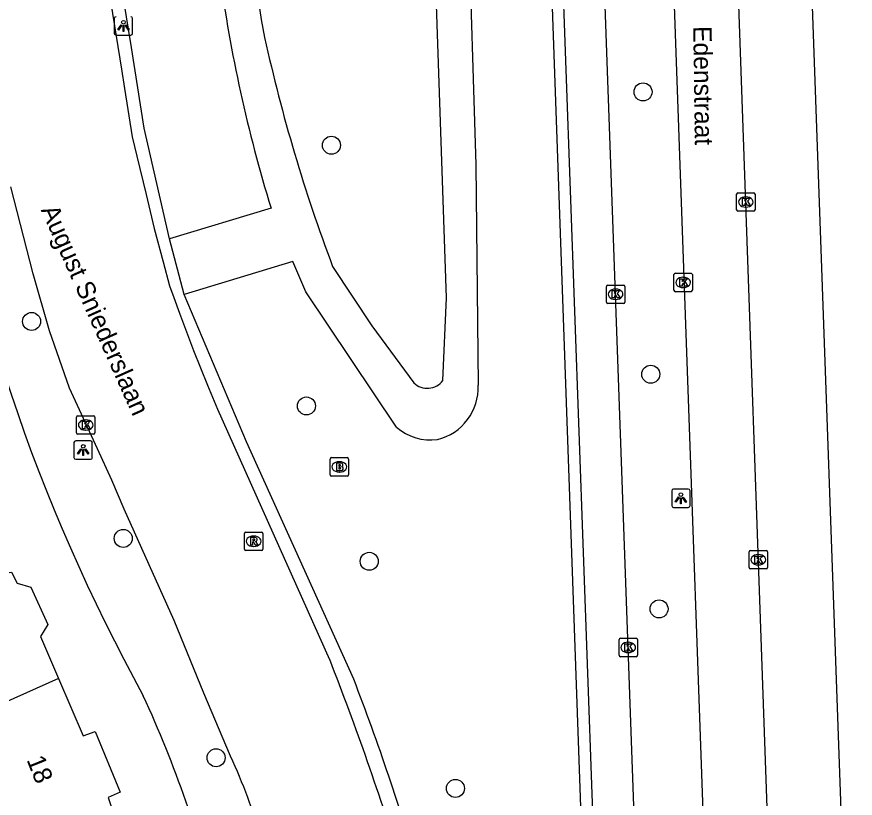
# Model space of a CAD drawing. Extents: x 160356 to 161355, y 381727 to 382845.
# Drawn here: x 161287.38 to 161332.94, y 382329.85 to 382372.29 of the extents above; entities that cross this region are included whole.
import ezdxf

# ---------------------------------------------------------------- set-up
doc = ezdxf.new("R2010")
doc.units = 0
for name, color, linetype in [('IMGEO_Boom', 7, 'Continuous'), ('IMGEO_Brandkraan', 7, 'Continuous'), ('IMGEO_Fietspad_gesloten', 7, 'Continuous'), ('IMGEO_Kolk', 7, 'Continuous'), ('IMGEO_Lichtpunt', 7, 'Continuous'), ('IMGEO_Openbare_ruimte_label', 7, 'Continuous'), ('IMGEO_Pand', 7, 'Continuous'), ('IMGEO_Pand_nummerreeks', 7, 'Continuous'), ('IMGEO_Rijbaan_lokaal_gesloten', 7, 'Continuous'), ('IMGEO_Rijbaan_lokaal_open', 7, 'Continuous'), ('IMGEO_Rioolput', 7, 'Continuous'), ('IMGEO_Voetpad_open', 7, 'Continuous')]:
    doc.layers.add(name, color=color, linetype=linetype)

msp = doc.modelspace()

# ---------------------------------------------------------------- linework, layer by layer
at = {"layer": 'IMGEO_Boom'}
for centre in [(161321.409, 382368.212), (161304.473, 382365.313), (161288.179, 382355.742), (161321.828, 382352.876), (161303.117, 382351.152), (161293.163, 382343.955), (161306.528, 382342.714), (161322.279, 382340.129), (161298.208, 382332.042), (161311.215, 382330.379)]:
    msp.add_circle(centre, 0.489, dxfattribs=at)
at = {"layer": 'IMGEO_Brandkraan'}
for p, q in [((161304.477, 382348.344), (161305.329, 382348.344)), ((161304.402, 382347.418), (161304.402, 382348.27)), ((161304.89, 382348.124), (161304.915, 382348.124)), ((161305.403, 382348.27), (161305.403, 382347.418)), ((161304.913, 382347.564), (161304.888, 382347.564)), ((161305.329, 382347.344), (161304.477, 382347.344))]:
    msp.add_line(p, q, dxfattribs=at)
for points in [[(161304.477, 382348.344), (161305.329, 382348.344)], [(161304.402, 382347.418), (161304.402, 382348.27)], [(161304.75, 382348.044), (161304.75, 382347.644), (161304.963, 382347.644)], [(161304.981, 382348.044), (161304.75, 382348.044)], [(161304.929, 382347.963), (161304.875, 382347.963), (161304.875, 382347.887)], [(161304.875, 382347.887), (161304.928, 382347.887)], [(161305.403, 382348.27), (161305.403, 382347.418)], [(161304.937, 382347.811), (161304.875, 382347.811), (161304.875, 382347.73)], [(161304.875, 382347.73), (161304.937, 382347.73)], [(161305.329, 382347.344), (161304.477, 382347.344)]]:
    msp.add_lwpolyline(points, dxfattribs=at)
for centre, radius, start, end in [((161304.479, 382348.268), 0.0765, 91.552, 178.448), ((161304.479, 382348.268), 0.0765, 91.552, 178.448), ((161305.327, 382348.268), 0.0765, 1.552, 88.448), ((161305.327, 382348.268), 0.0765, 1.552, 88.448), ((161304.93, 382347.925), 0.0379, 267.8285, 90.9355), ((161304.985, 382347.899), 0.145, 59.4692, 91.5367), ((161305.01, 382347.946), 0.0922, 285.5137, 58.1501), ((161305.015, 382347.754), 0.105, 301.3115, 78.989), ((161304.479, 382347.42), 0.0765, 181.552, 268.448), ((161304.479, 382347.42), 0.0765, 181.552, 268.448), ((161304.938, 382347.77), 0.0404, 269.8759, 90.5077), ((161304.969, 382347.895), 0.251, 268.6676, 293.5347), ((161305.327, 382347.42), 0.0765, 271.552, 358.448), ((161305.327, 382347.42), 0.0765, 271.552, 358.448)]:
    msp.add_arc(centre, radius, start, end, dxfattribs=at)
for centre, major_axis, ratio, start_param, end_param in [((161304.889, 382347.844), (-0.387, 0.002), 0.722429, 4.712389, 7.853982), ((161304.914, 382347.844), (-0.39, 0.002), 0.717154, 1.570796, 4.712389)]:
    msp.add_ellipse(centre, major_axis=major_axis, ratio=ratio, start_param=start_param, end_param=end_param, dxfattribs=at)
at = {"layer": 'IMGEO_Fietspad_gesloten'}
for points in [[(161321.926, 382301.113), (161318.45, 382398.178)], [(161322.18, 382266.442), (161320.188, 382290.699), (161319.95, 382294.602), (161319.771, 382298.34), (161319.579, 382303.861), (161316.294, 382395.637)]]:
    msp.add_lwpolyline(points, dxfattribs=at)
at = {"layer": 'IMGEO_Kolk'}
for p, q in [((161326.494, 382361.806), (161326.494, 382362.658)), ((161326.569, 382362.732), (161327.421, 382362.732)), ((161326.982, 382362.512), (161327.007, 382362.512)), ((161327.495, 382362.658), (161327.495, 382361.806)), ((161327.005, 382361.952), (161326.98, 382361.952)), ((161327.421, 382361.732), (161326.569, 382361.732)), ((161323.166, 382358.36), (161324.018, 382358.36)), ((161323.091, 382357.434), (161323.091, 382358.286)), ((161323.579, 382358.14), (161323.604, 382358.14)), ((161324.092, 382358.286), (161324.092, 382357.434)), ((161319.417, 382356.792), (161319.417, 382357.644)), ((161319.492, 382357.718), (161320.344, 382357.718)), ((161319.905, 382357.498), (161319.93, 382357.498)), ((161320.418, 382357.644), (161320.418, 382356.792)), ((161323.602, 382357.58), (161323.577, 382357.58)), ((161319.928, 382356.938), (161319.903, 382356.938)), ((161324.018, 382357.36), (161323.166, 382357.36)), ((161320.344, 382356.718), (161319.492, 382356.718)), ((161290.7, 382350.619), (161291.552, 382350.619)), ((161290.625, 382349.693), (161290.625, 382350.545)), ((161291.113, 382350.399), (161291.138, 382350.399)), ((161291.626, 382350.545), (161291.626, 382349.693)), ((161291.136, 382349.839), (161291.111, 382349.839)), ((161291.552, 382349.619), (161290.7, 382349.619)), ((161327.248, 382343.301), (161328.1, 382343.301)), ((161327.173, 382342.375), (161327.173, 382343.227)), ((161327.661, 382343.081), (161327.686, 382343.081)), ((161328.174, 382343.227), (161328.174, 382342.375)), ((161327.684, 382342.521), (161327.659, 382342.521)), ((161328.1, 382342.301), (161327.248, 382342.301)), ((161320.104, 382337.608), (161320.104, 382338.46)), ((161320.179, 382338.534), (161321.031, 382338.534)), ((161320.592, 382338.314), (161320.617, 382338.314)), ((161321.105, 382338.46), (161321.105, 382337.608)), ((161321.031, 382337.534), (161320.179, 382337.534)), ((161320.615, 382337.754), (161320.59, 382337.754))]:
    msp.add_line(p, q, dxfattribs=at)
for points in [[(161326.494, 382361.806), (161326.494, 382362.658)], [(161326.569, 382362.732), (161327.421, 382362.732)], [(161326.815, 382362.432), (161326.938, 382362.432), (161326.938, 382362.281), (161327.068, 382362.432), (161327.232, 382362.432), (161327.086, 382362.281), (161327.239, 382362.032), (161327.087, 382362.032), (161327.002, 382362.196), (161326.938, 382362.129), (161326.938, 382362.032), (161326.815, 382362.032), (161326.815, 382362.432)], [(161327.495, 382362.658), (161327.495, 382361.806)], [(161327.421, 382361.732), (161326.569, 382361.732)], [(161323.166, 382358.36), (161324.018, 382358.36)], [(161323.091, 382357.434), (161323.091, 382358.286)], [(161323.412, 382358.06), (161323.535, 382358.06), (161323.535, 382357.909), (161323.665, 382358.06), (161323.829, 382358.06), (161323.683, 382357.909), (161323.836, 382357.66), (161323.684, 382357.66), (161323.599, 382357.824), (161323.535, 382357.757), (161323.535, 382357.66), (161323.412, 382357.66), (161323.412, 382358.06)], [(161324.092, 382358.286), (161324.092, 382357.434)], [(161319.417, 382356.792), (161319.417, 382357.644)], [(161319.492, 382357.718), (161320.344, 382357.718)], [(161319.738, 382357.418), (161319.861, 382357.418), (161319.861, 382357.267), (161319.991, 382357.418), (161320.155, 382357.418), (161320.009, 382357.267), (161320.162, 382357.018), (161320.01, 382357.018), (161319.925, 382357.182), (161319.861, 382357.115), (161319.861, 382357.018), (161319.738, 382357.018), (161319.738, 382357.418)], [(161320.418, 382357.644), (161320.418, 382356.792)], [(161324.018, 382357.36), (161323.166, 382357.36)], [(161320.344, 382356.718), (161319.492, 382356.718)], [(161290.7, 382350.619), (161291.552, 382350.619)], [(161290.625, 382349.693), (161290.625, 382350.545)], [(161290.946, 382350.319), (161291.069, 382350.319), (161291.069, 382350.168), (161291.199, 382350.319), (161291.363, 382350.319), (161291.217, 382350.168), (161291.37, 382349.919), (161291.218, 382349.919), (161291.133, 382350.083), (161291.069, 382350.016), (161291.069, 382349.919), (161290.946, 382349.919), (161290.946, 382350.319)], [(161291.626, 382350.545), (161291.626, 382349.693)], [(161291.552, 382349.619), (161290.7, 382349.619)], [(161327.248, 382343.301), (161328.1, 382343.301)], [(161327.173, 382342.375), (161327.173, 382343.227)], [(161327.494, 382343.001), (161327.617, 382343.001), (161327.617, 382342.85), (161327.747, 382343.001), (161327.911, 382343.001), (161327.765, 382342.85), (161327.918, 382342.601), (161327.766, 382342.601), (161327.681, 382342.765), (161327.617, 382342.698), (161327.617, 382342.601), (161327.494, 382342.601), (161327.494, 382343.001)], [(161328.174, 382343.227), (161328.174, 382342.375)], [(161328.1, 382342.301), (161327.248, 382342.301)], [(161320.104, 382337.608), (161320.104, 382338.46)], [(161320.179, 382338.534), (161321.031, 382338.534)], [(161321.105, 382338.46), (161321.105, 382337.608)], [(161320.425, 382338.234), (161320.548, 382338.234), (161320.548, 382338.083), (161320.678, 382338.234), (161320.842, 382338.234), (161320.696, 382338.083), (161320.849, 382337.834), (161320.697, 382337.834), (161320.612, 382337.998), (161320.548, 382337.931), (161320.548, 382337.834), (161320.425, 382337.834), (161320.425, 382338.234)], [(161321.031, 382337.534), (161320.179, 382337.534)]]:
    msp.add_lwpolyline(points, dxfattribs=at)
for centre, start, end in [((161326.571, 382362.656), 91.552, 178.448), ((161326.571, 382362.656), 91.552, 178.448), ((161327.419, 382362.656), 1.552, 88.448), ((161327.419, 382362.656), 1.552, 88.448), ((161326.571, 382361.808), 181.552, 268.448), ((161326.571, 382361.808), 181.552, 268.448), ((161327.419, 382361.808), 271.552, 358.448), ((161327.419, 382361.808), 271.552, 358.448), ((161323.168, 382358.284), 91.552, 178.448), ((161323.168, 382358.284), 91.552, 178.448), ((161324.016, 382358.284), 1.552, 88.448), ((161324.016, 382358.284), 1.552, 88.448), ((161319.494, 382357.642), 91.552, 178.448), ((161319.494, 382357.642), 91.552, 178.448), ((161320.342, 382357.642), 1.552, 88.448), ((161320.342, 382357.642), 1.552, 88.448), ((161323.168, 382357.436), 181.552, 268.448), ((161323.168, 382357.436), 181.552, 268.448), ((161324.016, 382357.436), 271.552, 358.448), ((161324.016, 382357.436), 271.552, 358.448), ((161319.494, 382356.794), 181.552, 268.448), ((161319.494, 382356.794), 181.552, 268.448), ((161320.342, 382356.794), 271.552, 358.448), ((161320.342, 382356.794), 271.552, 358.448), ((161290.702, 382350.543), 91.552, 178.448), ((161290.702, 382350.543), 91.552, 178.448), ((161291.55, 382350.543), 1.552, 88.448), ((161291.55, 382350.543), 1.552, 88.448), ((161290.702, 382349.695), 181.552, 268.448), ((161290.702, 382349.695), 181.552, 268.448), ((161291.55, 382349.695), 271.552, 358.448), ((161291.55, 382349.695), 271.552, 358.448), ((161327.25, 382343.225), 91.552, 178.448), ((161327.25, 382343.225), 91.552, 178.448), ((161328.098, 382343.225), 1.552, 88.448), ((161328.098, 382343.225), 1.552, 88.448), ((161327.25, 382342.377), 181.552, 268.448), ((161327.25, 382342.377), 181.552, 268.448), ((161328.098, 382342.377), 271.552, 358.448), ((161328.098, 382342.377), 271.552, 358.448), ((161320.181, 382338.458), 91.552, 178.448), ((161320.181, 382338.458), 91.552, 178.448), ((161321.029, 382338.458), 1.552, 88.448), ((161321.029, 382338.458), 1.552, 88.448), ((161320.181, 382337.61), 181.552, 268.448), ((161320.181, 382337.61), 181.552, 268.448), ((161321.029, 382337.61), 271.552, 358.448), ((161321.029, 382337.61), 271.552, 358.448)]:
    msp.add_arc(centre, 0.0765, start, end, dxfattribs=at)
for centre, major_axis, ratio, start_param, end_param in [((161326.981, 382362.232), (-0.387, 0.002), 0.722429, 4.712389, 7.853982), ((161327.006, 382362.232), (-0.39, 0.002), 0.717154, 1.570796, 4.712389), ((161323.578, 382357.86), (-0.387, 0.002), 0.722429, 4.712389, 7.853982), ((161323.603, 382357.86), (-0.39, 0.002), 0.717154, 1.570796, 4.712389), ((161319.904, 382357.218), (-0.387, 0.002), 0.722429, 4.712389, 7.853982), ((161319.929, 382357.218), (-0.39, 0.002), 0.717154, 1.570796, 4.712389), ((161291.112, 382350.119), (-0.387, 0.002), 0.722429, 4.712389, 7.853982), ((161291.137, 382350.119), (-0.39, 0.002), 0.717154, 1.570796, 4.712389), ((161327.66, 382342.801), (-0.387, 0.002), 0.722429, 4.712389, 7.853982), ((161327.685, 382342.801), (-0.39, 0.002), 0.717154, 1.570796, 4.712389), ((161320.591, 382338.034), (-0.387, 0.002), 0.722429, 4.712389, 7.853982), ((161320.616, 382338.034), (-0.39, 0.002), 0.717154, 1.570796, 4.712389)]:
    msp.add_ellipse(centre, major_axis=major_axis, ratio=ratio, start_param=start_param, end_param=end_param, dxfattribs=at)
at = {"layer": 'IMGEO_Lichtpunt'}
for p, q in [((161292.675, 382372.197), (161292.675, 382371.39)), ((161292.675, 382372.197), (161292.675, 382371.39)), ((161293.671, 382371.39), (161293.671, 382372.197)), ((161293.671, 382371.39), (161293.671, 382372.197)), ((161292.769, 382371.296), (161293.577, 382371.296)), ((161292.769, 382371.296), (161293.577, 382371.296)), ((161291.388, 382349.258), (161290.58, 382349.258)), ((161291.388, 382349.258), (161290.58, 382349.258)), ((161290.486, 382349.163), (161290.486, 382348.356)), ((161290.486, 382349.163), (161290.486, 382348.356)), ((161291.482, 382348.356), (161291.482, 382349.163)), ((161291.482, 382348.356), (161291.482, 382349.163)), ((161290.58, 382348.262), (161291.388, 382348.262)), ((161290.58, 382348.262), (161291.388, 382348.262)), ((161322.967, 382346.544), (161322.967, 382345.737)), ((161322.967, 382346.544), (161322.967, 382345.737)), ((161323.869, 382346.639), (161323.061, 382346.639)), ((161323.869, 382346.639), (161323.061, 382346.639)), ((161323.963, 382345.737), (161323.963, 382346.544)), ((161323.963, 382345.737), (161323.963, 382346.544)), ((161323.061, 382345.643), (161323.869, 382345.643)), ((161323.061, 382345.643), (161323.869, 382345.643))]:
    msp.add_line(p, q, dxfattribs=at)
for points in [[(161293.049, 382371.861), (161293.088, 382371.833), (161292.9, 382371.571), (161292.862, 382371.598), (161293.049, 382371.861)], [(161293.151, 382371.813), (161293.198, 382371.813), (161293.198, 382371.491), (161293.151, 382371.491), (161293.151, 382371.813)], [(161293.261, 382371.833), (161293.299, 382371.86), (161293.486, 382371.598), (161293.447, 382371.57), (161293.261, 382371.833)], [(161290.86, 382348.827), (161290.899, 382348.799), (161290.711, 382348.537), (161290.673, 382348.564), (161290.86, 382348.827)], [(161290.962, 382348.779), (161291.009, 382348.779), (161291.009, 382348.457), (161290.962, 382348.457), (161290.962, 382348.779)], [(161291.072, 382348.799), (161291.11, 382348.826), (161291.297, 382348.564), (161291.258, 382348.536), (161291.072, 382348.799)], [(161323.341, 382346.208), (161323.38, 382346.18), (161323.192, 382345.918), (161323.154, 382345.945), (161323.341, 382346.208)], [(161323.443, 382346.16), (161323.49, 382346.16), (161323.49, 382345.838), (161323.443, 382345.838), (161323.443, 382346.16)], [(161323.553, 382346.18), (161323.591, 382346.207), (161323.778, 382345.945), (161323.739, 382345.917), (161323.553, 382346.18)]]:
    msp.add_lwpolyline(points, dxfattribs=at)
for centre in [(161293.174, 382371.995), (161290.985, 382348.961), (161323.466, 382346.342)]:
    msp.add_circle(centre, 0.0994, dxfattribs=at)
for centre, start, end in [((161292.769, 382372.197), 90, 180), ((161292.769, 382372.197), 90, 180), ((161293.577, 382372.197), 0, 90), ((161293.577, 382372.197), 0, 90), ((161292.769, 382371.39), 180, 270), ((161292.769, 382371.39), 180, 270), ((161293.577, 382371.39), 270, 0), ((161293.577, 382371.39), 270, 360), ((161290.58, 382349.163), 90, 180), ((161290.58, 382349.163), 90, 180), ((161291.388, 382349.163), 0, 90), ((161291.388, 382349.163), 0, 90), ((161290.58, 382348.356), 180, 270), ((161290.58, 382348.356), 180, 270), ((161291.388, 382348.356), 270, 0), ((161291.388, 382348.356), 270, 360), ((161323.061, 382346.544), 90, 180), ((161323.061, 382346.544), 90, 180), ((161323.869, 382346.544), 0, 90), ((161323.869, 382346.544), 0, 90), ((161323.061, 382345.737), 180, 270), ((161323.061, 382345.737), 180, 270), ((161323.869, 382345.737), 270, 0), ((161323.869, 382345.737), 270, 360)]:
    msp.add_arc(centre, 0.0946, start, end, dxfattribs=at)
at = {"layer": 'IMGEO_Pand'}
for points in [[(161286.734, 382342.07), (161287.094, 382342.13), (161287.405, 382341.521), (161288.136, 382341.304), (161289.071, 382339.287), (161288.674, 382338.636), (161289.652, 382336.355)], [(161289.652, 382336.355), (161278.18, 382331.222)], [(161289.652, 382336.355), (161290.99, 382333.235), (161291.629, 382333.467), (161292.998, 382330.172), (161292.349, 382329.89), (161292.775, 382328.604)]]:
    msp.add_lwpolyline(points, dxfattribs=at)
at = {"layer": 'IMGEO_Rijbaan_lokaal_gesloten'}
for points in [[(161329.384, 382295.255), (161328.927, 382307.262), (161325.875, 382393.982)], [(161330.052, 382388.106), (161332.941, 382307.348)], [(161322.615, 382386.648), (161325.857, 382295.549)]]:
    msp.add_lwpolyline(points, dxfattribs=at)
at = {"layer": 'IMGEO_Rijbaan_lokaal_open'}
for points in [[(161291.373, 382388.848), (161291.728, 382379.174), (161291.904, 382376.636), (161293.075, 382369.451), (161293.226, 382368.403), (161293.652, 382365.778), (161293.903, 382364.721), (161294.414, 382362.637), (161294.843, 382360.791), (161295.331, 382358.987), (161295.674, 382357.671), (161295.918, 382357.039), (161296.22, 382356.194), (161296.989, 382354.165), (161297.743, 382352.273), (161298.287, 382350.973), (161304.379, 382337.386)], [(161298.994, 382332.13), (161297.539, 382335.546), (161295.93, 382339.49), (161293.77, 382344.297), (161293.217, 382345.548), (161292.55, 382347.123), (161291.766, 382348.825), (161290.242, 382352.118), (161289.151, 382355.236), (161288.259, 382358.335), (161287.062, 382363.053)]]:
    msp.add_lwpolyline(points, dxfattribs=at)
for centre, radius, start, end in [((161150.656, 382277.305), 165.048, 17.22565, 21.34761), ((161269.995, 382318.742), 31.94, 16.0709, 24.7813)]:
    msp.add_arc(centre, radius, start, end, dxfattribs=at)
at = {"layer": 'IMGEO_Rioolput'}
for p, q in [((161299.747, 382343.377), (161299.747, 382344.229)), ((161299.822, 382344.303), (161300.674, 382344.303)), ((161300.748, 382344.229), (161300.748, 382343.377)), ((161300.235, 382344.083), (161300.26, 382344.083)), ((161300.674, 382343.303), (161299.822, 382343.303)), ((161300.258, 382343.523), (161300.233, 382343.523))]:
    msp.add_line(p, q, dxfattribs=at)
for points in [[(161299.747, 382343.377), (161299.747, 382344.229)], [(161299.822, 382344.303), (161300.674, 382344.303)], [(161300.748, 382344.229), (161300.748, 382343.377)], [(161300.336, 382344.001), (161300.084, 382344.003), (161300.084, 382343.603)], [(161300.084, 382343.603), (161300.208, 382343.603), (161300.208, 382343.765), (161300.219, 382343.765)], [(161300.262, 382343.922), (161300.208, 382343.922), (161300.208, 382343.841)], [(161300.208, 382343.841), (161300.26, 382343.841)], [(161300.266, 382343.736), (161300.337, 382343.603), (161300.477, 382343.603), (161300.412, 382343.729)], [(161300.674, 382343.303), (161299.822, 382343.303)]]:
    msp.add_lwpolyline(points, dxfattribs=at)
for centre, radius, start, end in [((161299.824, 382344.227), 0.0765, 91.552, 178.448), ((161299.824, 382344.227), 0.0765, 91.552, 178.448), ((161300.672, 382344.227), 0.0765, 1.552, 88.448), ((161300.672, 382344.227), 0.0765, 1.552, 88.448), ((161300.218, 382343.712), 0.0533, 26.0293, 88.6989), ((161300.244, 382344.03), 0.19, 274.7715, 282.9687), ((161300.268, 382343.826), 0.0964, 77.0061, 93.1865), ((161300.282, 382343.883), 0.0378, 276.6634, 79.6772), ((161300.335, 382343.891), 0.109, 350.3612, 89.416), ((161300.333, 382343.891), 0.112, 277.5842, 350.9817), ((161300.317, 382343.676), 0.108, 29.5134, 73.7905), ((161299.824, 382343.379), 0.0765, 181.552, 268.448), ((161299.824, 382343.379), 0.0765, 181.552, 268.448), ((161300.672, 382343.379), 0.0765, 271.552, 358.448), ((161300.672, 382343.379), 0.0765, 271.552, 358.448)]:
    msp.add_arc(centre, radius, start, end, dxfattribs=at)
for centre, major_axis, ratio, start_param, end_param in [((161300.234, 382343.803), (-0.387, 0.002), 0.722429, 4.712389, 7.853982), ((161300.259, 382343.803), (-0.39, 0.002), 0.717154, 1.570796, 4.712389)]:
    msp.add_ellipse(centre, major_axis=major_axis, ratio=ratio, start_param=start_param, end_param=end_param, dxfattribs=at)
at = {"layer": 'IMGEO_Voetpad_open'}
for points in [[(161315.724, 382393.755), (161318.911, 382303.837), (161319.103, 382298.321), (161319.292, 382294.513), (161319.526, 382290.746), (161321.423, 382267.645)], [(161295.68, 382360.226), (161294.307, 382366.234), (161293.603, 382370.626), (161292.915, 382374.857), (161292.69, 382376.721), (161292.498, 382379.219), (161292.42, 382380.899), (161292.222, 382387.065)], [(161311.444, 382384.238), (161311.904, 382377.704), (161312.321, 382364.259), (161312.45, 382352.275)], [(161310.533, 382352.533), (161310.72, 382357.027), (161310.025, 382377.746)], [(161301.197, 382361.892), (161295.68, 382360.226)], [(161296.481, 382357.212), (161295.68, 382360.226)], [(161308.015, 382349.999), (161303.078, 382357.36), (161302.371, 382359.005), (161296.481, 382357.212)], [(161304.541, 382358.728), (161306.671, 382355.513), (161308.959, 382352.409)], [(161305.687, 382336.317), (161299.862, 382349.199), (161296.481, 382357.212)]]:
    msp.add_lwpolyline(points, dxfattribs=at)
for centre, radius, start, end in [((161323.585, 382375.929), 23.233, 172.1606, 191.838), ((161376.526, 382385.109), 78.826, 187.65656, 197.12991), ((161389.412, 382390.713), 90.698, 192.44809, 200.65003), ((161381.976, 382383.685), 100.128, 188.32347, 208.82203), ((161309.691, 382353.163), 1.051, 225.8256, 323.1833), ((161309.554, 382352.152), 2.898, 283.5832, 2.428), ((161309.857, 382352.113), 2.804, 228.9413, 277.7549), ((161181.842, 382288.633), 132.708, 16.22253, 21.05837), ((161232.24, 382307.005), 68.209, 14.22551, 24.61338)]:
    msp.add_arc(centre, radius, start, end, dxfattribs=at)

# ---------------------------------------------------------------- texts
at = {"layer": 'IMGEO_Openbare_ruimte_label'}
for s, rotation, p in [('Edenstraat', 270.8021, (161324.138, 382371.779)), ('August Sniederslaan', 294.0788, (161288.671, 382361.801))]:
    msp.add_text(s, height=1, rotation=rotation, dxfattribs=at).set_placement(p)
at = {"layer": 'IMGEO_Pand_nummerreeks'}
msp.add_text('18', height=1, rotation=291.9473, dxfattribs=at).set_placement((161287.897, 382331.933))

doc.saveas('drawing.dxf')
